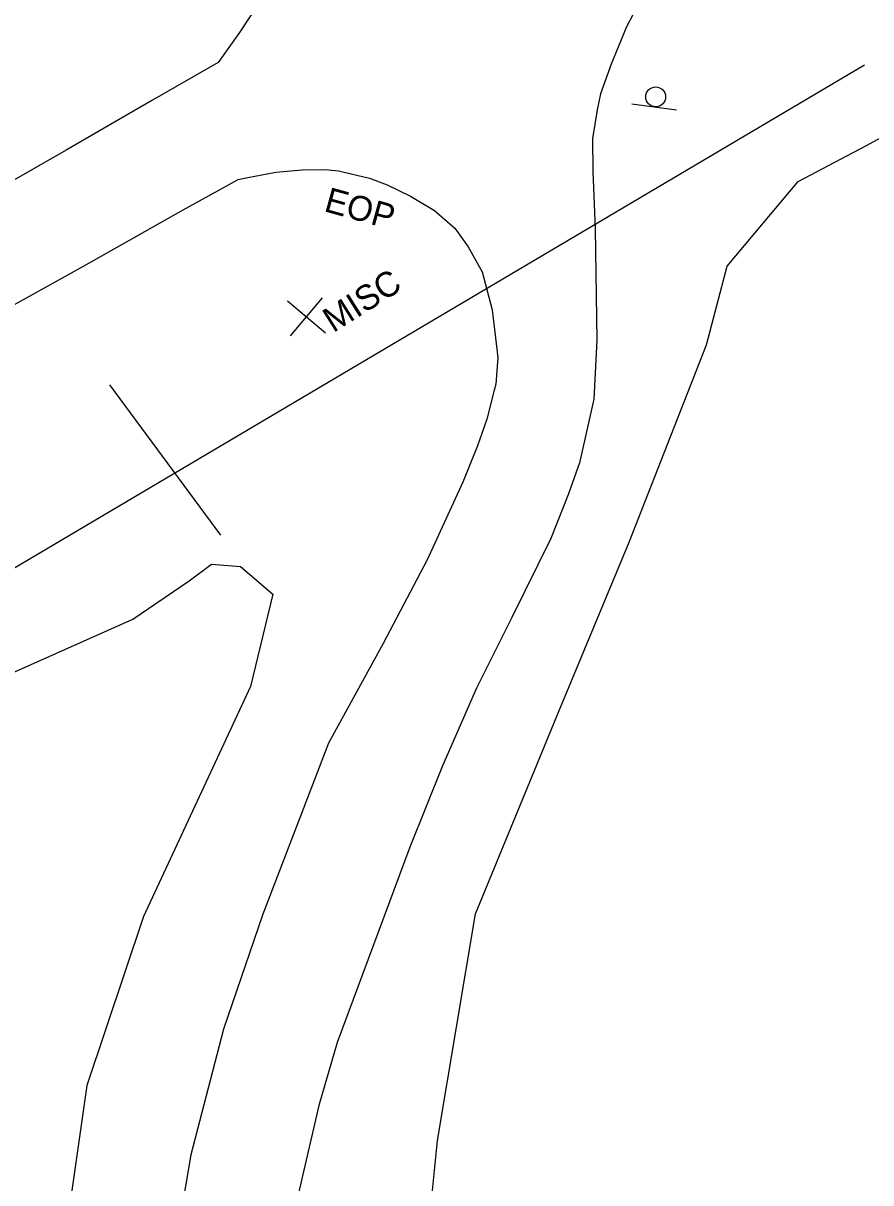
# Model space of a CAD drawing. Extents: x 2076109 to 2080761, y 592812 to 596750.
# Drawn here: x 2077726 to 2077896.2, y 595822.6 to 596055.5 of the extents above; entities that cross this region are included whole.
import ezdxf

# ---------------------------------------------------------------- set-up
doc = ezdxf.new("R2010")
doc.units = 0
for name, color, linetype in [('RD_EX_BldgApp', 7, 'Continuous'), ('RD_EX_Fence_Other', 7, 'Continuous'), ('RD_EX_Misc', 7, 'Continuous'), ('RD_EX_Misc_txCode', 7, 'Continuous'), ('RD_EX_Road', 7, 'Continuous'), ('RD_EX_Road_txCode', 7, 'Continuous'), ('RD_EX_UT', 7, 'Continuous'), ('RD_EX_VEG', 7, 'Continuous')]:
    doc.layers.add(name, color=color, linetype=linetype)

msp = doc.modelspace()

# ---------------------------------------------------------------- linework, layer by layer
at = {"layer": 'RD_EX_BldgApp'}
msp.add_line((2077848.23, 596039.36), (2077857.14, 596038.11), dxfattribs=at)
msp.add_line((2077848.23, 596039.36), (2077857.14, 596038.11), dxfattribs=at)
msp.add_circle((2077852.99, 596040.74), 2, dxfattribs=at)
msp.add_circle((2077852.99, 596040.74), 2, dxfattribs=at)
at = {"layer": 'RD_EX_Fence_Other'}
msp.add_line((2077765.71, 595952.68), (2077743.4, 595982.88), dxfattribs=at)
msp.add_line((2077765.71, 595952.68), (2077743.4, 595982.88), dxfattribs=at)
at = {"layer": 'RD_EX_Misc'}
for p, q in [((2077779.05, 595999.77), (2077786.68, 595993.31)), ((2077779.05, 595999.77), (2077786.68, 595993.31)), ((2077779.64, 595992.73), (2077786.1, 596000.36)), ((2077779.64, 595992.73), (2077786.1, 596000.36))]:
    msp.add_line(p, q, dxfattribs=at)
at = {"layer": 'RD_EX_Road'}
for points in [[(2077849.67, 596059.65), (2077847.15, 596054.79), (2077844.03, 596047.3), (2077841.89, 596041.35), (2077841.21, 596038.16), (2077840.27, 596032.38), (2077840.39, 596025.72), (2077840.85, 596014.26), (2077841.15, 595991.85), (2077840.55, 595979.99), (2077837.71, 595967.21), (2077835.51, 595961.03), (2077831.91, 595952.04), (2077824.11, 595936.14), (2077817, 595921.98), (2077810.2, 595906.36), (2077803.62, 595890), (2077789.01, 595850.8), (2077785.39, 595838.15), (2077781.1, 595819.63)], [(2077849.67, 596059.65), (2077847.15, 596054.79), (2077844.03, 596047.3), (2077841.89, 596041.35), (2077841.21, 596038.16), (2077840.27, 596032.38), (2077840.39, 596025.72), (2077840.85, 596014.26), (2077841.15, 595991.85), (2077840.55, 595979.99), (2077837.71, 595967.21), (2077835.51, 595961.03), (2077831.91, 595952.04), (2077824.11, 595936.14), (2077817, 595921.98), (2077810.2, 595906.36), (2077803.62, 595890), (2077789.01, 595850.8), (2077785.39, 595838.15), (2077781.1, 595819.63)], [(2077772.92, 596058.93), (2077769.46, 596053.64), (2077765.13, 596047.65), (2077751.94, 596040.06), (2077734.63, 596030.03), (2077714.84, 596018.75), (2077688.54, 596003.96), (2077665.9, 595991.28), (2077650.73, 595982.79), (2077619.31, 595965.17), (2077602.41, 595955.62), (2077586.04, 595946.49), (2077564.37, 595934.19), (2077543.8, 595922.59), (2077519.41, 595908.81)], [(2077772.92, 596058.93), (2077769.46, 596053.64), (2077765.13, 596047.65), (2077751.94, 596040.06), (2077734.63, 596030.03), (2077714.84, 596018.75), (2077688.54, 596003.96), (2077665.9, 595991.28), (2077650.73, 595982.79), (2077619.31, 595965.17), (2077602.41, 595955.62), (2077586.04, 595946.49), (2077564.37, 595934.19), (2077543.8, 595922.59), (2077519.41, 595908.81)], [(2077718.14, 595995.67), (2077738.13, 596006.73), (2077758.15, 596018.05), (2077769.19, 596024.14), (2077770.75, 596024.47), (2077776.75, 596025.64), (2077782.02, 596026.11), (2077786.66, 596026.17), (2077789.33, 596025.89), (2077795.52, 596024.42), (2077799.1, 596023.05), (2077803.79, 596020.78), (2077808.56, 596017.94), (2077812.64, 596014.34), (2077815.32, 596010.61), (2077818.13, 596005.57), (2077820.13, 595997.94), (2077821.32, 595988.38), (2077820.87, 595983.02), (2077820.58, 595981.8), (2077819.1, 595975.98), (2077817.22, 595970.67), (2077814.25, 595963.35), (2077807.08, 595947.77), (2077798.28, 595930.91), (2077787.28, 595910.9), (2077774.11, 595876.55), (2077766.22, 595853.44), (2077759.66, 595828.2), (2077756.72, 595810.93)], [(2077718.14, 595995.67), (2077738.13, 596006.73), (2077758.15, 596018.05), (2077769.19, 596024.14), (2077770.75, 596024.47), (2077776.75, 596025.64), (2077782.02, 596026.11), (2077786.66, 596026.17), (2077789.33, 596025.89), (2077795.52, 596024.42), (2077799.1, 596023.05), (2077803.79, 596020.78), (2077808.56, 596017.94), (2077812.64, 596014.34), (2077815.32, 596010.61), (2077818.13, 596005.57), (2077820.13, 595997.94), (2077821.32, 595988.38), (2077820.87, 595983.02), (2077820.58, 595981.8), (2077819.1, 595975.98), (2077817.22, 595970.67), (2077814.25, 595963.35), (2077807.08, 595947.77), (2077798.28, 595930.91), (2077787.28, 595910.9), (2077774.11, 595876.55), (2077766.22, 595853.44), (2077759.66, 595828.2), (2077756.72, 595810.93)]]:
    msp.add_lwpolyline(points, dxfattribs=at)
at = {"layer": 'RD_EX_UT'}
msp.add_line((2077528.24, 595830.07), (2077894.89, 596047.18), dxfattribs=at)
msp.add_line((2077528.24, 595830.07), (2077894.89, 596047.18), dxfattribs=at)
at = {"layer": 'RD_EX_VEG'}
for points in [[(2077881.48, 595666.18), (2077859.01, 595664.31), (2077829.44, 595671.5), (2077817.19, 595682.23), (2077804.91, 595704.21), (2077805.61, 595737.62), (2077804.88, 595788.24), (2077809.18, 595831.11), (2077816.84, 595876.65), (2077833.48, 595917.17), (2077847.66, 595951.31), (2077863.18, 595990.93), (2077867.34, 596006.71), (2077881.56, 596023.72), (2077895.2, 596030.93), (2077937.59, 596053.88)], [(2077881.48, 595666.18), (2077859.01, 595664.31), (2077829.44, 595671.5), (2077817.19, 595682.23), (2077804.91, 595704.21), (2077805.61, 595737.62), (2077804.88, 595788.24), (2077809.18, 595831.11), (2077816.84, 595876.65), (2077833.48, 595917.17), (2077847.66, 595951.31), (2077863.18, 595990.93), (2077867.34, 596006.71), (2077881.56, 596023.72), (2077895.2, 596030.93), (2077937.59, 596053.88)], [(2077537.58, 595809.49), (2077586.06, 595839.41), (2077638.97, 595865.22), (2077665.91, 595880.11), (2077674.35, 595893.56), (2077702.2, 595915.39), (2077747.99, 595935.83), (2077759.3, 595943.54), (2077763.8, 595946.9), (2077769.61, 595946.39), (2077776.15, 595940.86), (2077771.62, 595922.27), (2077750.18, 595876.07), (2077738.76, 595842.17), (2077732.42, 595797.53)], [(2077537.58, 595809.49), (2077586.06, 595839.41), (2077638.97, 595865.22), (2077665.91, 595880.11), (2077674.35, 595893.56), (2077702.2, 595915.39), (2077747.99, 595935.83), (2077759.3, 595943.54), (2077763.8, 595946.9), (2077769.61, 595946.39), (2077776.15, 595940.86), (2077771.62, 595922.27), (2077750.18, 595876.07), (2077738.76, 595842.17), (2077732.42, 595797.53)]]:
    msp.add_lwpolyline(points, dxfattribs=at)

# ---------------------------------------------------------------- texts
at = {"layer": 'RD_EX_Misc_txCode'}
msp.add_text(' MISC', height=5, rotation=32.2429, dxfattribs=at).set_placement((2077786.68, 595992.28))
msp.add_text(' MISC', height=5, rotation=32.2429, dxfattribs=at).set_placement((2077786.68, 595992.28))
at = {"layer": 'RD_EX_Road_txCode'}
msp.add_text('EOP', height=5, rotation=344.5467, dxfattribs=at).set_placement((2077786.19, 596017.82))
msp.add_text('EOP', height=5, rotation=344.5467, dxfattribs=at).set_placement((2077786.19, 596017.82))

doc.saveas('drawing.dxf')
